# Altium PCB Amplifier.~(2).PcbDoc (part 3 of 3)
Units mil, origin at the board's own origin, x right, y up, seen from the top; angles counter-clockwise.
Board outline 9055.12 x 4724.41 mil, 2 copper layers (Top Layer, Bottom Layer); 154 components, 83 nets, 405 pads, 1525 vias.
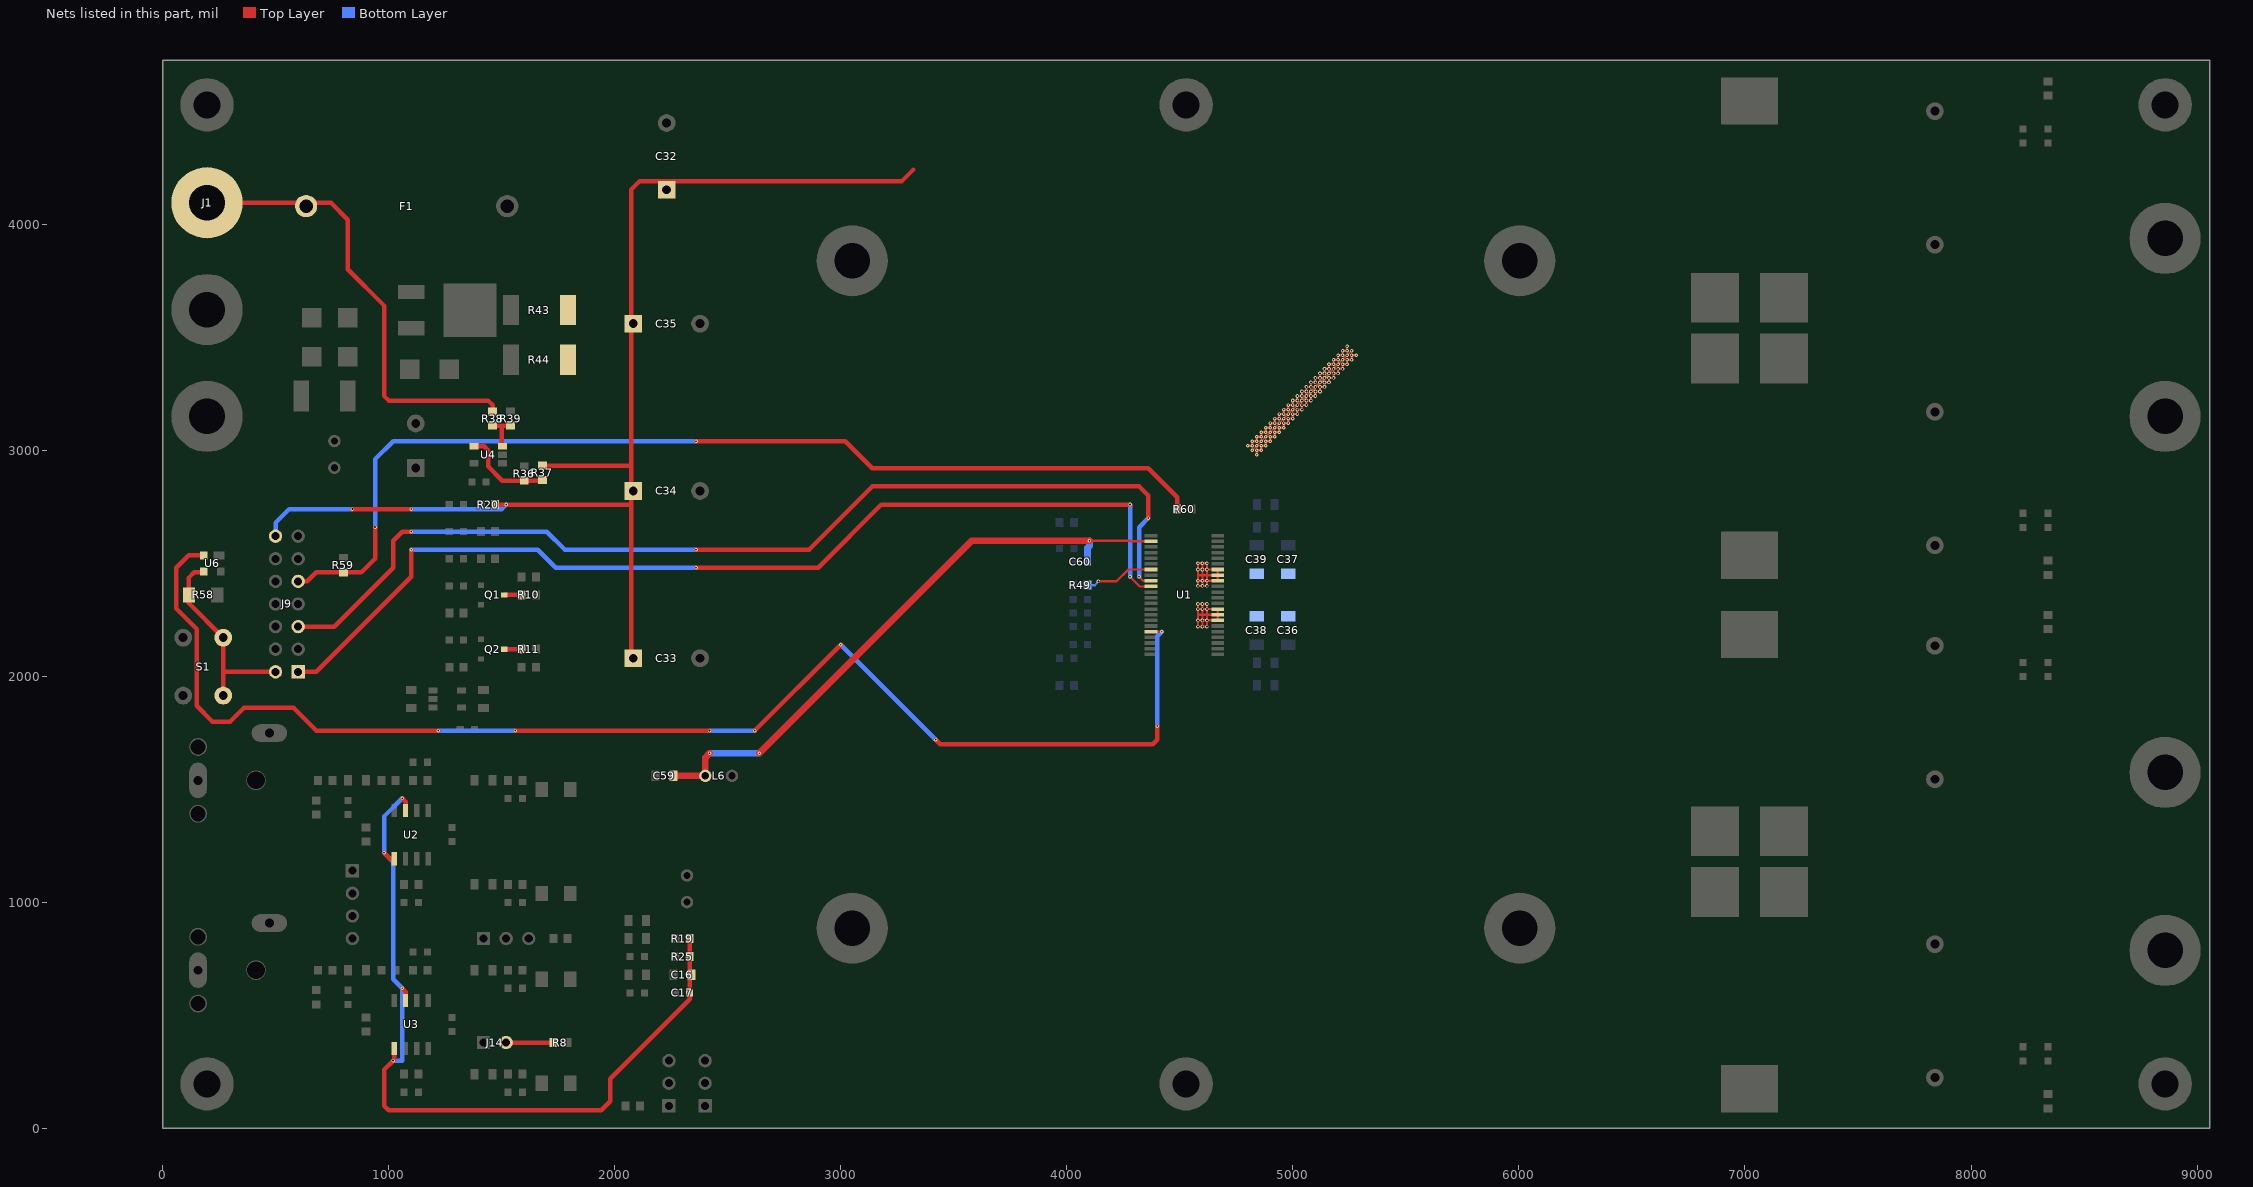
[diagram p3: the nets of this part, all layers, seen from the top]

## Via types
v1: diameter 15.75, hole 7.87, Top Layer to Bottom Layer, 1525 vias

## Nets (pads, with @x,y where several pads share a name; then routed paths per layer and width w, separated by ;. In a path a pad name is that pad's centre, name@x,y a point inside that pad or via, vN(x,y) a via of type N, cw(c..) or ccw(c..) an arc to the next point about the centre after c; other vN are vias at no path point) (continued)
NetJ14_2: J14.2 R8.2 | length 208.5
  Top Layer w20: J14.2@1520,380 R8.2@1728.5,380
NetQ1_1: Q1.1 R10.1 | length 77.3
  Top Layer w20: Q1.1@1511.18,2360 R10.1@1588.5,2360
NetQ2_1: Q2.1 R11.1 | length 77.3
  Top Layer w20: Q2.1@1511.18,2120 R11.1@1588.5,2120
NetR36_2: R36.2 R37.2 U4.4 | length 408.2
  Top Layer w20: U4.4@1377.01,3017.4 1422.6,3017.4 1440,3000 1440,2928.5 1502.99,2865.51 R37.2@1680.39,2865.51
NetR38_2: R38.2 R39.1 U4.3 | length 146.8
  Top Layer w20: R38.2@1468.5,3108.5 1500,3108.5 ; U4.3@1502.99,3025.91 1500,3028.9 1500,3108.5 ; R39.1@1531.5,3108.5 1500,3108.5
NetR49_2: R49.2 U1.7 | length 309.6
  Top Layer w10: v1(4140,2420) 4220,2420 4272.5,2472.5 U1.7@4372.36,2472.5
  Bottom Layer w10: R49.2@4091.5,2403.13 4123.13,2403.13 v1(4140,2420)
OSC_IOM: J9.5 U1.9 | length 4606.1
  Top Layer w10: v1(4320,2440) 4337.5,2422.5 U1.9@4372.36,2422.5
  Top Layer w20: J9.5@600,2220 760,2220 1020,2480 1020,2600 1060,2640 v1(1100,2640) ; v1(2360,2560) 2860,2560 3140,2840 4320,2840 4360,2800 v1(4360,2700)
  Bottom Layer w20: v1(1100,2640) 1700,2640 1780,2560 v1(2360,2560) ; v1(4320,2440) 4320,2660 v1(4360,2700)
OSC_IOP: J9.1 U1.10 | length 4553.1
  Top Layer w10: v1(4280,2440) 4322.5,2397.5 U1.10@4372.36,2397.5
  Top Layer w20: J9.1@600,2020 680,2020 1100,2440 v1(1100,2560) ; v1(2360,2480) 2900,2480 3180,2760 v1(4280,2760)
  Bottom Layer w20: v1(1100,2560) 1660,2560 1740,2480 v1(2360,2480) ; v1(4280,2440) v1(4280,2760)
PVDD: C32.1 C33.1 C34.1 C35.1 C36.1 C37.1 C38.1 C39.1 J9.14 R20.1 R37.1 R43.2 R44.2 U1.29 U1.30 U1.31 U1.36 U1.37 U1.38 | length 9190.7
  Top Layer w10: v1(4800,3020) v1(4820,3020) v1(4820,3040) v1(4840,3040) v1(4840,3060) v1(4860,3060) v1(4860,3080) v1(4880,3080) v1(4880,3100) v1(4900,3100) v1(4900,3120) v1(4920,3120) v1(4920,3140) v1(4940,3140) v1(4940,3160) v1(4960,3160) v1(4960,3180) v1(4980,3180) v1(4980,3200) v1(5000,3200) v1(5000,3220) v1(5020,3220) v1(5020,3240) v1(5040,3240) v1(5040,3260) v1(5060,3260) v1(5060,3280) v1(5080,3280) v1(5080,3300) v1(5100,3300) v1(5100,3320) v1(5120,3320) v1(5120,3340) v1(5140,3340) v1(5140,3360) v1(5160,3360) v1(5160,3380) v1(5180,3380) v1(5180,3400) v1(5200,3400) v1(5200,3420) v1(5220,3420) v1(5220,3440) v1(5240,3440) v1(5240,3460) ; v1(4820,3000) v1(4840,3020) v1(4860,3040) v1(4880,3060) v1(4900,3080) v1(4920,3100) v1(4940,3120) v1(4960,3140) v1(4980,3160) v1(5000,3180) v1(5020,3200) v1(5040,3220) v1(5060,3240) v1(5080,3260) v1(5100,3280) v1(5120,3300) v1(5140,3320) v1(5160,3340) v1(5180,3360) v1(5200,3380) v1(5220,3400) v1(5240,3420) v1(5260,3440) ; v1(4840,2980) v1(4840,3000) v1(4860,3000) v1(4860,3020) v1(4880,3020) v1(4880,3040) v1(4900,3040) v1(4900,3060) v1(4920,3060) v1(4920,3080) v1(4940,3080) v1(4940,3100) v1(4960,3100) v1(4960,3120) v1(4980,3120) v1(4980,3140) v1(5000,3140) v1(5000,3160) v1(5020,3160) v1(5020,3180) v1(5040,3180) v1(5040,3200) v1(5060,3200) v1(5060,3220) v1(5080,3220) v1(5080,3240) v1(5100,3240) v1(5100,3260) v1(5120,3260) v1(5120,3280) v1(5140,3280) v1(5140,3300) v1(5160,3300) v1(5160,3320) v1(5180,3320) v1(5180,3340) v1(5200,3340) v1(5200,3360) v1(5220,3360) v1(5220,3380) v1(5240,3380) v1(5240,3400) v1(5260,3400) v1(5260,3420) v1(5280,3420) ; v1(4580,2247.5) v1(4600,2247.5) ; v1(4580,2247.5) 4580,2272.5 ; v1(4580,2247.5) v1(4580,2220) v1(4600,2220) ; 4580,2272.5 4600,2272.5 ; 4580,2272.5 v1(4580,2297.5) ; v1(4580,2297.5) v1(4600,2297.5) ; v1(4580,2297.5) v1(4580,2320) v1(4600,2320) ; v1(4580,2422.5) v1(4600,2422.5) ; v1(4580,2422.5) 4580,2447.5 ; v1(4580,2422.5) v1(4580,2400) v1(4600,2400) ; 4580,2447.5 v1(4580,2472.5) ; 4580,2447.5 4600,2447.5 ; v1(4580,2472.5) v1(4600,2472.5) ; v1(4580,2472.5) v1(4580,2500) v1(4600,2500) ; v1(4600,2220) v1(4600,2247.5) ; v1(4600,2220) v1(4620,2220) v1(4620,2247.5) ; v1(4600,2247.5) v1(4620,2247.5) ; v1(4600,2247.5) 4600,2272.5 ; 4600,2272.5 4620,2272.5 ; 4600,2272.5 v1(4600,2297.5) ; v1(4600,2297.5) v1(4620,2297.5) ; v1(4600,2297.5) v1(4600,2320) ; v1(4600,2320) v1(4620,2320) v1(4620,2297.5) ; v1(4600,2400) v1(4600,2422.5) ; v1(4600,2400) v1(4620,2400) v1(4620,2422.5) ; v1(4600,2422.5) v1(4620,2422.5) ; v1(4600,2422.5) 4600,2447.5 ; 4600,2447.5 4620,2447.5 ; 4600,2447.5 v1(4600,2472.5) ; v1(4600,2472.5) v1(4620,2472.5) ; v1(4600,2472.5) v1(4600,2500) ; v1(4600,2500) v1(4620,2500) v1(4620,2472.5) ; v1(4620,2247.5) U1.29@4667.64,2247.5 U1.30@4667.64,2272.5 ; v1(4620,2247.5) 4620,2272.5 ; 4620,2272.5 U1.30@4667.64,2272.5 ; 4620,2272.5 v1(4620,2297.5) ; v1(4620,2297.5) U1.31@4667.64,2297.5 U1.30@4667.64,2272.5 ; v1(4620,2422.5) U1.36@4667.64,2422.5 U1.37@4667.64,2447.5 ; v1(4620,2422.5) 4620,2447.5 ; 4620,2447.5 U1.37@4667.64,2447.5 ; 4620,2447.5 v1(4620,2472.5) ; v1(4620,2472.5) U1.38@4667.64,2472.5 U1.37@4667.64,2447.5
  Top Layer w20: v1(840,2740) v1(1100,2740) ; R20.1@1471.5,2760 v1(1520,2760) 2072.36,2760 ; R37.1@1680,2930.87 2072.36,2930.87 ; 2072.36,2120 2072.36,2760 ; 3320,4240 3270.72,4190.72 2110.72,4190.72 2072.36,4152.36 2072.36,2930.87 ; 2072.36,2760 2072.36,2930.87
  Bottom Layer w20: J9.14@500,2620 500,2680 560,2740 v1(840,2740) ; v1(1100,2740) 1500,2740 v1(1520,2760)
PVin: F1.1 J1.1 R38.1 | length 2025.4
  Top Layer w20: J1.1@196.85,4094.49 745.51,4094.49 820,4020 820,3800 980,3640 980,3240 1000,3220 1440,3220 1460,3200 R38.1@1460,3171.5
R\E\S\E\T\: J9.2 R58.1 S1.2 U6.3 | length 893.1
  Top Layer w20: U6.3@182.6,2464.57 178.03,2460 140,2460 117.01,2437.01 R58.1@117.01,2360 117.01,2322.58 S1.2@268.58,2171 268.58,2020 ; S1.2@268.58,1915.1 268.58,2020 ; J9.2@500,2020 268.58,2020
R\E\S\E\T\_amp: U1.18 U6.2 | length 6019.5
  Top Layer w10: U1.18@4372.36,2197.5 v1(4420,2197.5)
  Top Layer w20: U6.2@182.6,2535.43 115.43,2535.43 60,2480 60,2300 150.79,2209.21 150.79,1869.21 220,1800 300,1800 360,1860 580,1860 680,1760 v1(1220,1760) ; v1(1560,1760) v1(2420,1760) ; v1(2620,1760) v1(3000,2140) ; v1(3420,1720) 3440,1700 4380,1700 4400,1720 v1(4400,1780)
  Bottom Layer w20: v1(1220,1760) v1(1560,1760) ; v1(2420,1760) v1(2620,1760) ; v1(3000,2140) v1(3420,1720) ; v1(4400,1780) 4400,2177.5 v1(4420,2197.5)
Temp: J9.9 R59.2 R60.2 | length 4557.5
  Top Layer w20: J9.9@600,2420 640,2420 680,2460 R59.2@800,2460 880,2460 940,2520 v1(940,2660) ; v1(2360,3040) 3020,3040 3140,2920 4360,2920 4488.5,2791.5 R60.2@4488.5,2740
  Bottom Layer w20: v1(940,2660) 940,2960 1020,3040 v1(2360,3040)
VDD: C59.1 C60.1 L6.2 U1.2 | length 2689.5
  Top Layer w10: v1(4100,2600) 4280,2600 4282.5,2597.5 U1.2@4372.36,2597.5
  Top Layer w30: C59.1@2259.37,1560 L6.2@2400.94,1560 2400.94,1640.94 v1(2420,1660) ; v1(2640,1660) 3580,2600 v1(4100,2600)
  Bottom Layer w30: v1(2420,1660) v1(2640,1660) ; C60.1@4091.5,2506.26 4091.5,2568.5 4100,2577.01 v1(4100,2600)
VMID: C16.1 C17.1 R19.2 R25.1 U2.3 U2.5 U3.3 U3.5 | length 3594.8
  Top Layer w20: v1(980,1220) 1006.3,1193.7 U2.5@1025,1193.7 ; U3.5@1025,353.7 1025,305 v1(1020,300) 980,260 980,100 1000,80 1940,80 1980,120 1980,220 2331.5,571.5 R19.2@2331.5,830 ; v1(1060,620) 1075,605 U3.3@1075,566.3 ; v1(1060,1460) 1075,1445 U2.3@1075,1406.3
  Bottom Layer w20: v1(1020,300) 1060,300 v1(1060,620) 1020,660 1020,1180 v1(980,1220) 980,1380 v1(1060,1460)
pads on no net: J7. J8. L2.3 L3.3 L5.3 L7.3

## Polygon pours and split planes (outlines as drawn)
NetD6_2 on Top Layer "Vin_protected" (solid, pour order 18): 1220,3280 1220,3440 1220,4280 1600,4280 1600,3280
PVin on Top Layer "PVin" (solid, pour order 17): 0,3920 840,3920 840,4280 0,4280
NetC66_1 on Top Layer "OUT_D" (solid, pour order 3): 9040,340 7060,340 7060,1160 9040,1160
NetC53_1 on Top Layer "OUT_C" (solid, pour order 2): 9040,1200 7060,1200 7060,2020 9040,2020
NetC43_1 on Top Layer "OUT_B" (solid, pour order 1): 9040,2700 7060,2700 7060,3520 9040,3520
NetC27_1 on Top Layer "OUT_A" (solid, pour order 0): 9040,3560 7060,3560 7060,4380 9040,4380
NetC51_2 on Top Layer "OUT_C_top" (solid, pour order 6): 4704.43,2329.43 4640,2329.43 4640,2315 4725,2315 4760,2280 4840,2280 5120,2000 5640,2000 6440,1200 6980,1200 6980,2020 6400,2020 6090.57,2329.43
NetC52_2 on Top Layer "OUT_D_top" (solid, pour order 7): 4640,2190 4770,2190 4800.77,2159.23 4800,1900 5085.09,1620 5500,1620 6780,340 6980,340 6980,1160 6400,1160 5760,1800 5600,1960 5080,1960 4810,2230 4640,2230
NetC40_1 on Top Layer "OUT_B_top" (solid, pour order 5): 4705,2390 4640,2390 4640,2405 4725,2405 4760,2440 4840,2440 5120,2720 5640,2720 6440,3520 6980,3520 6980,2700 6400,2700 6090,2390
NetC41_1 on Top Layer "OUT_A_top" (solid, pour order 4): 4640,2530 4770,2530 4800,2560 4800,2820 5080,3100 5500,3100 6780,4380 6980,4380 6980,3560 6400,3560 5599.88,2759.88 5080.39,2760.39 4810,2490 4640,2490
PVDD on Top Layer "PVVD2_top" (solid, pour order 20): 4570,2210 4570,2330 4630,2330 4630,2310 4700,2310 4700,2240 4630,2240 4630,2210
PVDD on Top Layer "PVVD2_top" (solid, pour order 21): 4570,2390 4570,2510 4630,2510 4630,2480 4700,2480 4700,2410 4630,2410 4630,2390
PVDD on Top Layer "PVDD" (solid, pour order 19): 3039.61,4280 3040,4279.61 4440.4,4279.61 5300,3420 4840,2960 4139.61,3660.39 3479.61,3660.39 2640.39,3660.39 2640,3660 2300,3660 2300,1960 1740,1960 1740,3060 1740,4280
+12Vin on Top Layer "+12Vin" (solid, pour order 16): 20,3320 20,2980 480,2980 660,3160 660,3320
GND on Top Layer "GND_top" (solid, pour order 43): 0,0 0,4724.41 9055.12,4724.41 9055.12,0
PVDD on Bottom Layer "PVDD2_bottom" (solid, pour order 22): 4780,3020 5100,2700 5100,2580 5030,2510 4560,2510 4560,2390 4740,2390 4740,2330 4560,2330 4560,2210 5270,2210 5500,2440 5500,3220 5240,3480
GND on Bottom Layer "GND_bottom" (solid, pour order 44): 0,0 0,4724.41 9055.12,4724.41 9055.12,0

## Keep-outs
Keep-Out Layer:
  the board outline again, w10

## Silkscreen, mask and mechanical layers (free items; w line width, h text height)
Top Overlay:
  rectangle: 3760,100 4300,200
  lines w10: 2800,200 4300,200 ; 3000,100 3000,400 4300,400 4300,100 2800,100 2800,300 4300,300 ; 3380,100 3380,400 ; 3760,100 3760,400 ; 4760,200 5720,200 ; 4960,100 4960,400 5720,400 5720,300 ; 5340,100 5340,400 ; 5720,300 5720,100 4760,100 4760,300 5720,300 ; 0,0 9055.12,0 9055.12,4724.41 0,4724.41 0,0 ; 2657.48,492.13 6397.64,492.13 6397.64,4232.28 2657.48,4232.28 2657.48,492.13
  text "MAA : Amplifier V1.1" at 600,4600 h60
  text "aerith.fr" at 600,4500 h60
  text "+18-53.5V" at 420,4360 h60 r270
  text "10A F" at 980,4340 h60
  text "GND" at 420,3700 h60 r270
  text "Left" at 8980,3440 h60 r90
  text "+12V" at 420,3260 h60 r270
  text "PVDD" at 920,2720 h60
  text "+12V" at 920,2600 h60
  text "+3V3" at 920,2480 h60
  text "FAULT" at 920,2360 h60
  text "RESET" at 40,2240 h60
  text "CLIP" at 920,2160 h60
  text "OTW" at 920,2080 h60
  text "Left" at 60,1240 h60
  text "Right" at 8980,1060 h60 r90
  text "1" at 1400,900 h30
  text "1" at 1360,440 h30
  text "Right" at 60,400 h60
  text "none" at 3000,300 h60
  text "1-2" at 3380,300 h60
  text "2-3" at 3760,300 h60
  text "1-2" at 4960,300 h60
  text "2-3" at 5340,300 h60
  text "J10" at 2800,200 h60
  text "stereo" at 3000,200 h60
  text "mono" at 3380,200 h60
  text "right OFF" at 3760,200 h60
  text "J11" at 4760,200 h60
  text "mono" at 4960,200 h60
  text "stereo" at 5340,200 h60
  text "J14" at 2800,100 h60
  text "stereo" at 3000,100 h60
  text "mono" at 3380,100 h60
  text "J12" at 4760,100 h60
  text "master" at 4960,100 h60
  text "slave" at 5340,100 h60
  text "1" at 2160,60 h30
  text "1" at 2460,60 h30
Drill Drawing:
  the board outline again, w10

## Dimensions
0,0 to 9055.12,0 on Mechanical 2
9055.12,0 to 9055.12,4724.41 on Mechanical 2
